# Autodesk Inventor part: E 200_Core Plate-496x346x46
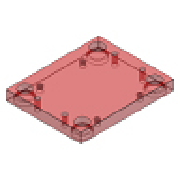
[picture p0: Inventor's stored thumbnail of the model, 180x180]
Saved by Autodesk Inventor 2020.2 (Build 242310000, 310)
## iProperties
Manager: www.cadconsulting.pl
Company: Fabian Stasiak CAD Consulting
IsCustomPart: 1
Created: 2014-02
Part Number: E 200_Core Plate-496x346x46
Material: S 55 C
Description: Core Plate
Document SubType Name: Modeling
Designer: F.Stasiak
Standard Revision: 1
Manufacturer: DME
Language: pl-PL
Size Designation: 496x346x46
Categories: <MemberInstance><Categories><Category DisplayName="Forma wtryskowa" InternalName="349578f2-f4d4-4954-8c09-8e99297a61c0" Mnemonic="MOLD"><Category DisplayName="P
Density: 7.85 g/cm^3
Appearance: Dark Red
Catalog Web Link: www.expertbooks.pl
Author: F.Stasiak
Subject: Zbiór ćwiczeń. Autodesk Inventor 2020. Kurs Professional
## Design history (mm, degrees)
sketch "Sketch1"
  geometry: L1 (-173, 248)-(173, 248); L2 (173, 248)-(173, -248); L3 (173, -248)-(-173, -248); L4 (-173, -248)-(-173, 248); 6 further points
  constraints: 8 end point, 2 midpoint, 2 parallel, 1 horizontal, 1 horizontal alignment, 1 perpendicular, 1 vertical alignment
  dimensions: "d123" = 346 distance between parallel lines of L2 L4 (= W_); "d124" = 496 distance between parallel lines of L3 L1 (= L); "d125" = 95 horizontal distance of point (0, 0) point (-95, 233) (= 0.5 x RP_W); "d126" = 233 vertical distance of point (0, 0) point (-95, 233) (= 0.5 x RP_L); "d127" = 137 horizontal distance of point (0, 0) point (-137, 208) (= 0.5 x GB_W); "d128" = 208 vertical distance of point (0, 0) point (-137, 208) (= 0.5 x GB_L); "d129" = 165 vertical distance of point (0, 0) point (-137, 165) (= 0.5 x S1_L); "d130" = 137 horizontal distance of point (0, 0) point (-137, 165) (= 0.5 x S1_W)
extrude "Extrusion1" new body sketch "Sketch1" distance "d20" = 46 (= H_); taper "d30" = 0 deg
hole "Hole1" sketch "Sketch1" diameter "d131" = 13.835; stored, may be unused: countersink angle "d135" = 90 deg, drill point angle "d137" = 118 deg; dims "d132" = 24.5 (= H_l), "d133" = 4, "d134" = 2, "d136" = 25 (= H_u)
pattern_linear "Rectangular Pattern1" dims "d140" = 330 (computed from S1_L, Ns), "d143" = 274 (computed from S1_W, Nw)
hole "Hole2" sketch "Sketch1" diameter "d144" = 42 (= GB_d1); stored, may be unused: countersink angle "d148" = 90 deg, drill point angle "d150" = 0 deg; dims "d145" = 6, "d146" = 48 (= GB_d2), "d147" = 6 (= GB_k), "d149" = 46 (= H_)
pattern_linear "Rectangular Pattern2" dims "d153" = 416 (computed from GB_L, Nl), "d156" = 274 (computed from GB_W, Nw)
hole "Hole3" sketch "Sketch1" diameter "d157" = 14 (= RP_dt); stored, may be unused: countersink angle "d161" = 90 deg, drill point angle "d163" = 0 deg; dims "d158" = 6, "d159" = 48 (= GB_d2), "d160" = 6 (= GB_k), "d162" = 46 (= H_)
pattern_linear "Rectangular Pattern3" dims "d166" = 466 (computed from RP_L, Nl), "d169" = 190 (computed from RP_W, Nw)
chamfer "Chamfer1" distance "d170" = 0.5; stored, may be unused: second distance "d171" = 2, angle "d172" = 45 deg
sketch "Szkic2"
  geometry: L1 (-78, -154.488)-(-78, 154.488); L2 (72.488, -160)-(-72.488, -160); L3 (78, 154.488)-(78, -154.488); L4 (-72.488, 160)-(72.488, 160); A1 r 4 centre (-75.879, 157.879) between (-72.488, 160) and (-78, 154.488); A2 r 4 centre (-75.879, -157.879) between (-78, -154.488) and (-72.488, -160); A3 r 4 centre (75.879, -157.879) between (72.488, -160) and (78, -154.488); A4 r 4 centre (75.879, 157.879) between (78, 154.488) and (72.488, 160)
  constraints: 8 end point, 8 point on circle, 4 centre point
extrude "Wyciągnięcie proste2" cut sketch "Szkic2" distance "d177" = 60; taper "d178" = 0 deg
sketch "Szkic3"
  geometry: 1 further point
hole "Otwór12" sketch "Szkic3" at (0, 0) diameter "d179" = 4.5; stored, may be unused: countersink angle "d183" = 90 deg, drill point angle "d185" = 0 deg; dims "d180" = 6, "d181" = 4, "d182" = 2, "d184" = 8
sketch "Szkic4"
  geometry: 4 further points
hole "Otwór13" sketch "Szkic4" at (-54, 134), (-24, -134), (24, 134), (54, -134) diameter "d186" = 5; stored, may be unused: countersink angle "d190" = 90 deg, drill point angle "d192" = 0 deg; dims "d187" = 6, "d188" = 4, "d189" = 2, "d191" = 8
sketch "Szkic5"
  geometry: 4 further points
hole "Otwór14" sketch "Szkic5" at (-24, 134), (-54, -134), (54, 134), (24, -134) diameter "d193" = 5; stored, may be unused: countersink angle "d197" = 90 deg, drill point angle "d199" = 0 deg; dims "d194" = 6, "d195" = 4, "d196" = 2, "d198" = 8
sketch "Szkic6"
  geometry: 4 further points
hole "Otwór15" sketch "Szkic6" at (-54, 103.5), (-24, -103.5), (24, 103.5), (54, -103.5) diameter "d200" = 5; stored, may be unused: countersink angle "d204" = 90 deg, drill point angle "d206" = 0 deg; dims "d201" = 6, "d202" = 4, "d203" = 2, "d205" = 8
sketch "Szkic7"
  geometry: 4 further points
hole "Otwór16" sketch "Szkic7" at (-24, 103.5), (-54, -103.5), (54, 103.5), (24, -103.5) diameter "d207" = 5; stored, may be unused: countersink angle "d211" = 90 deg, drill point angle "d213" = 0 deg; dims "d208" = 6, "d209" = 4, "d210" = 2, "d212" = 8
sketch "Szkic8"
  geometry: 4 further points
hole "Otwór17" sketch "Szkic8" at (-47, 71.2), (-31, -71.2), (31, 71.2), (47, -71.2) diameter "d214" = 5; stored, may be unused: countersink angle "d218" = 90 deg, drill point angle "d220" = 0 deg; dims "d215" = 6, "d216" = 4, "d217" = 2, "d219" = 8
sketch "Szkic9"
  geometry: 4 further points
hole "Otwór18" sketch "Szkic9" at (-31, 71.2), (-47, -71.2), (47, 71.2), (31, -71.2) diameter "d221" = 5; stored, may be unused: countersink angle "d225" = 90 deg, drill point angle "d227" = 0 deg; dims "d222" = 6, "d223" = 4, "d224" = 2, "d226" = 8
sketch "Szkic10"
  geometry: 4 further points
hole "Otwór19" sketch "Szkic10" at (-48.5, 54), (-29.5, -54), (29.5, 54), (48.5, -54) diameter "d228" = 5; stored, may be unused: countersink angle "d232" = 90 deg, drill point angle "d234" = 0 deg; dims "d229" = 6, "d230" = 4, "d231" = 2, "d233" = 8
sketch "Szkic11"
  geometry: 4 further points
hole "Otwór20" sketch "Szkic11" at (-29.5, 54), (-48.5, -54), (48.5, 54), (29.5, -54) diameter "d235" = 5; stored, may be unused: countersink angle "d239" = 90 deg, drill point angle "d241" = 0 deg; dims "d236" = 6, "d237" = 4, "d238" = 2, "d240" = 8
sketch "Szkic12"
  geometry: 4 further points
hole "Otwór21" sketch "Szkic12" at (-57, 29), (-21, -29), (21, 29), (57, -29) diameter "d242" = 5; stored, may be unused: countersink angle "d246" = 90 deg, drill point angle "d248" = 0 deg; dims "d243" = 6, "d244" = 4, "d245" = 2, "d247" = 8
sketch "Szkic13"
  geometry: 4 further points
hole "Otwór22" sketch "Szkic13" at (-39, 35), (-39, -35), (39, 35), (39, -35) diameter "d249" = 5; stored, may be unused: countersink angle "d253" = 90 deg, drill point angle "d255" = 0 deg; dims "d250" = 6, "d251" = 4, "d252" = 2, "d254" = 8
sketch "Szkic14"
  geometry: 4 further points
hole "Otwór23" sketch "Szkic14" at (-21, 29), (-57, -29), (57, 29), (21, -29) diameter "d256" = 5; stored, may be unused: countersink angle "d260" = 90 deg, drill point angle "d262" = 0 deg; dims "d257" = 6, "d258" = 4, "d259" = 2, "d261" = 8
node "Płaszczyzna konstrukcyjna6"
node "Punkt konstrukcyjny8"
node "Płaszczyzna konstrukcyjna7"
node "Punkt konstrukcyjny9"
node "Płaszczyzna konstrukcyjna8"
node "Punkt konstrukcyjny10"
node "Płaszczyzna konstrukcyjna9"
node "Punkt konstrukcyjny11"
feature "Rzeźbienie21"
feature "Rzeźbienie22"
feature "Rzeźbienie23"
feature "Rzeźbienie24"
feature "Rzeźbienie25"
feature "Rzeźbienie26"
feature "Rzeźbienie27"
feature "Rzeźbienie28"
feature "Rzeźbienie29"
feature "Rzeźbienie30"
feature "Rzeźbienie31"
feature "Rzeźbienie32"
feature "Rzeźbienie33"
feature "Rzeźbienie34"
feature "Rzeźbienie35"
feature "Rzeźbienie36"
feature "Rzeźbienie37"
feature "Rzeźbienie38"
feature "Rzeźbienie39"
feature "Rzeźbienie40"
feature "Rzeźbienie41"
feature "Rzeźbienie42"
node "Płaszczyzna konstrukcyjna10"
node "Płaszczyzna konstrukcyjna11"
body "Solid1"
feature "Powierzchnia21"
body "Srf21"
feature "Powierzchnia22"
body "Srf22"
feature "Powierzchnia23"
body "Srf23"
feature "Powierzchnia24"
body "Srf24"
feature "Powierzchnia25"
body "Srf25"
feature "Powierzchnia26"
body "Srf26"
feature "Powierzchnia27"
body "Srf27"
feature "Powierzchnia28"
body "Srf28"
feature "Powierzchnia29"
body "Srf29"
feature "Powierzchnia30"
body "Srf30"
feature "Powierzchnia31"
body "Srf31"
feature "Powierzchnia32"
body "Srf32"
feature "Powierzchnia33"
body "Srf33"
feature "Powierzchnia34"
body "Srf34"
feature "Powierzchnia35"
body "Srf35"
feature "Powierzchnia36"
body "Srf36"
feature "Powierzchnia37"
body "Srf37"
feature "Powierzchnia38"
body "Srf38"
feature "Powierzchnia39"
body "Srf39"
feature "Powierzchnia40"
body "Srf40"
feature "Powierzchnia41"
body "Srf41"
feature "Powierzchnia42"
body "Srf42"
other parameters: "L" = 496 [user parameter; used in 1 equation term], "W_" = 346 [user parameter; used in 1 equation term], "H_" = 46 [user parameter; used in 3 equation terms], "GB_W" = 274 [user parameter; used in 2 equation terms], "GB_d1" = 42 [user parameter; used in 1 equation term], "GB_d2" = 48 [user parameter; used in 2 equation terms], "GB_k" = 6 [user parameter; used in 2 equation terms], "S1_W" = 274 [user parameter; used in 2 equation terms], "RP_L" = 466 [user parameter; used in 2 equation terms], "RP_dt" = 14 [user parameter; used in 1 equation term], "GB_L" = 416 [user parameter; used in 2 equation terms], "le" = 24 [user parameter], "ke" = 33 [user parameter], "H_u" = 25 [user parameter; used in 1 equation term], "H_l" = 24.5 [user parameter; used in 1 equation term], "d176" = 25.8085
